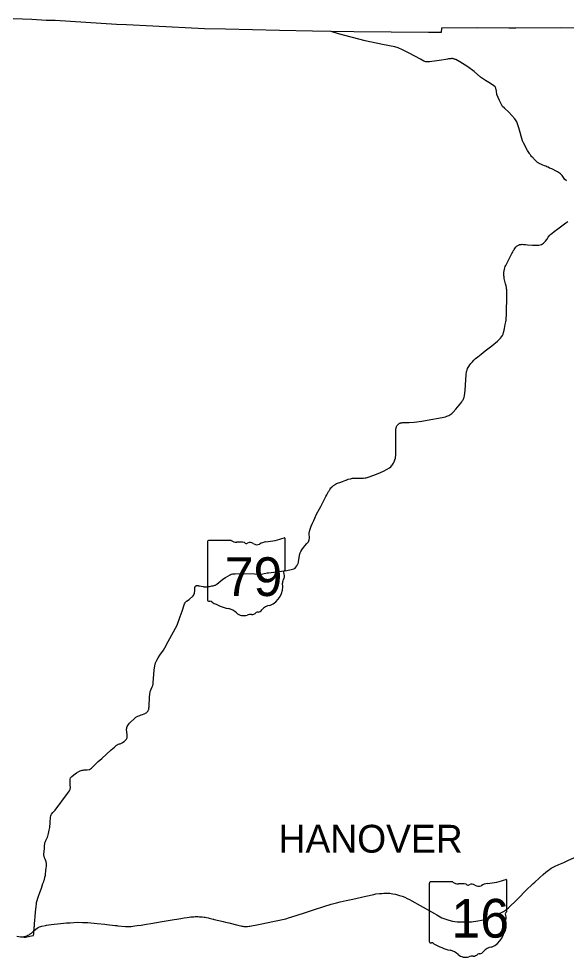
# Model space of a CAD drawing. Extents: x 1761803 to 2441803, y 509895 to 949895.
# Drawn here: x 1999264 to 2038611, y 844157 to 911653 of the extents above; entities that cross this region are included whole.
import ezdxf

# ---------------------------------------------------------------- set-up
doc = ezdxf.new("R2010")
doc.units = 0
for name, color, linetype in [('GM_X_County', 7, 'Continuous'), ('GM_X_County_Road', 7, 'Continuous'), ('GM_X_Minor_Lake', 7, 'Continuous'), ('GM_X_Township_Road', 7, 'Continuous')]:
    doc.layers.add(name, color=color, linetype=linetype)

msp = doc.modelspace()

# ---------------------------------------------------------------- linework, layer by layer
at = {"layer": 'GM_X_County'}
msp.add_lwpolyline([(2053400, 910687), (2048066, 910835), (2042725, 910935), (2038298, 911006), (2034985, 910966), (2034493, 910970), (2032253, 910990), (2029643, 910984), (2029631, 910665), (2029362, 910671), (2028709, 910661), (2023356, 910714), (2021728, 910742), (2020383, 910765), (2017999, 910806), (2014117, 910901), (2012614, 910938), (2008904, 911114), (2007002, 911215), (2006296, 911251), (2001880, 911522), (2001221, 911534), (2000194, 911593), (1998869, 911653)], dxfattribs=at)
at = {"layer": 'GM_X_County_Road'}
msp.add_line((2022502, 852839), (2022502, 852839), dxfattribs=at)
msp.add_line((2022502, 852839), (2022502, 852839), dxfattribs=at)
msp.add_line((2022502, 852839), (2022502, 852839), dxfattribs=at)
at = {"layer": 'GM_X_Minor_Lake'}
for points in [[(2038621, 899990), (2038489, 900117), (2038405, 900228), (2038314, 900373), (2038192, 900506), (2037995, 900646), (2037588, 900856), (2037420, 900914), (2037310, 900968), (2037219, 901010), (2037143, 901046), (2037055, 901079), (2036941, 901125), (2036843, 901162), (2036776, 901191), (2036722, 901216), (2036672, 901241), (2036631, 901265), (2036588, 901290), (2036550, 901322), (2036488, 901375), (2036459, 901404), (2036416, 901447), (2036374, 901490), (2036340, 901532), (2036268, 901599), (2036225, 901642), (2036166, 901707), (2036119, 901758), (2036077, 901810), (2036033, 901866), (2035996, 901920), (2035967, 901971), (2035831, 902189), (2035546, 902727), (2035474, 902862), (2035199, 903805), (2035071, 904238), (2034908, 904460), (2034490, 904935), (2034177, 905221), (2034031, 905349), (2033809, 905765), (2033616, 906198), (2033604, 906450), (2033562, 906659), (2033506, 906747), (2033414, 906831), (2033171, 906987), (2032809, 907211), (2032455, 907459), (2031990, 907857), (2031540, 908195), (2030955, 908563), (2030673, 908714), (2030634, 908735), (2030581, 908755), (2030522, 908772), (2030481, 908781), (2030432, 908784), (2030366, 908787), (2030311, 908783), (2030246, 908777), (2030160, 908764), (2030070, 908750), (2029959, 908734), (2029654, 908686), (2029302, 908633), (2028789, 908552), (2028645, 908551), (2028515, 908560), (2028381, 908609), (2028126, 908739), (2027312, 909168), (2026847, 909423), (2026534, 909571), (2026283, 909638), (2025407, 909794), (2024156, 910073), (2022247, 910574), (2021728, 910742)], [(2022788, 878480), (2022937, 878529), (2023097, 878573), (2023188, 878591), (2023239, 878601), (2023366, 878610), (2023560, 878614), (2023847, 878617), (2024051, 878620), (2024168, 878630), (2024240, 878642), (2024439, 878701), (2024772, 878836), (2025099, 878956), (2025469, 879109), (2025731, 879251), (2025919, 879366), (2026006, 879438), (2026061, 879496), (2026100, 879540), (2026193, 879694), (2026247, 879789), (2026304, 879928), (2026332, 880055), (2026347, 880134), (2026360, 880239), (2026364, 880430), (2026364, 881533), (2026367, 882066), (2026370, 882127), (2026375, 882165), (2026382, 882207), (2026392, 882248), (2026402, 882291), (2026420, 882326), (2026441, 882367), (2026463, 882399), (2026481, 882431), (2026501, 882456), (2026523, 882477), (2026546, 882501), (2026576, 882524), (2026609, 882546), (2026637, 882560), (2026672, 882575), (2026707, 882586), (2026740, 882593), (2026784, 882602), (2026836, 882608), (2026946, 882611), (2027326, 882608), (2027672, 882630), (2028226, 882720), (2028885, 882829), (2029423, 882926), (2029806, 882996), (2029939, 883030), (2030036, 883064), (2030168, 883127), (2030249, 883176), (2030391, 883273), (2030494, 883369), (2030677, 883566), (2031043, 884006), (2031111, 884095), (2031166, 884188), (2031202, 884252), (2031274, 884427), (2031303, 884527), (2031332, 884740), (2031350, 884909), (2031373, 885324), (2031412, 886042), (2031434, 886274), (2031481, 886391), (2031524, 886491), (2031618, 886652), (2031692, 886758), (2031764, 886852), (2031877, 886974), (2031981, 887090), (2032095, 887209), (2032248, 887341), (2032499, 887540), (2032787, 887772), (2033267, 888121), (2033669, 888462), (2033799, 888575), (2033893, 888674), (2033962, 888782), (2034021, 888881), (2034067, 888977), (2034104, 889100), (2034149, 889252), (2034179, 889378), (2034234, 889676), (2034266, 889847), (2034288, 889978), (2034304, 890109), (2034315, 890326), (2034321, 890678), (2034336, 891512), (2034339, 891965), (2034333, 892152), (2034328, 892223), (2034316, 892314), (2034288, 892441), (2034242, 892599), (2034202, 892776), (2034159, 892972), (2034140, 893085), (2034131, 893161), (2034126, 893263), (2034119, 893404), (2034140, 893523), (2034164, 893637), (2034193, 893738), (2034233, 893847), (2034259, 893899), (2034705, 894762), (2034764, 894873), (2034807, 894956), (2034834, 895008), (2034866, 895065), (2034913, 895142), (2034958, 895203), (2034995, 895244), (2035029, 895276), (2035060, 895303), (2035089, 895324), (2035129, 895351), (2035180, 895377), (2035218, 895393), (2035258, 895407), (2035304, 895418), (2035343, 895424), (2035387, 895428), (2035437, 895430), (2035529, 895423), (2035600, 895419), (2035691, 895412), (2035833, 895397), (2036192, 895380), (2036404, 895370), (2036648, 895370), (2036732, 895383), (2036823, 895420), (2036911, 895465), (2036973, 895508), (2037060, 895583), (2037111, 895646), (2037220, 895786), (2037322, 895938), (2037435, 896079), (2037514, 896154), (2037572, 896204), (2037742, 896346), (2038002, 896545), (2038385, 896832), (2038580, 896972), (2038719, 897066)], [(2021768, 877981), (2021814, 878023), (2021873, 878073), (2021921, 878110), (2021968, 878142), (2022035, 878182), (2022105, 878219), (2022242, 878275), (2022347, 878312), (2022521, 878372), (2022763, 878472), (2022788, 878480)], [(2019302, 872412), (2019318, 872441), (2019335, 872484), (2019366, 872562), (2019375, 872628), (2019394, 872735), (2019441, 873048), (2019468, 873160), (2019491, 873233), (2019546, 873334), (2019605, 873448), (2019665, 873541), (2019744, 873640), (2019832, 873752), (2019979, 873919), (2020078, 874038), (2020134, 874176), (2020154, 874316), (2020149, 874407), (2020144, 874511), (2020140, 874597), (2020144, 874693), (2020154, 874762), (2020186, 874873), (2020234, 875015), (2020290, 875165), (2020376, 875368), (2020462, 875573), (2020532, 875737), (2020672, 876025), (2020879, 876403), (2020971, 876578), (2021072, 876778), (2021116, 876862), (2021208, 877044), (2021335, 877283), (2021397, 877403), (2021457, 877511), (2021528, 877645), (2021564, 877708), (2021592, 877754), (2021609, 877782), (2021653, 877846), (2021702, 877911), (2021757, 877971), (2021768, 877981)], [(2001335, 852807), (2001354, 852859), (2001385, 852955), (2001408, 853047), (2001457, 853297), (2001495, 853490), (2001523, 853839), (2001543, 854233), (2001559, 854323), (2001587, 854391), (2001625, 854443), (2001722, 854560), (2001877, 854725), (2002763, 855932), (2002918, 856132), (2002941, 856176), (2002957, 856217), (2002963, 856253), (2002970, 856353), (2002968, 856531), (2002958, 856763), (2002955, 856808), (2002953, 856859), (2002961, 856971), (2002991, 857069), (2003081, 857163), (2003227, 857287), (2003419, 857426), (2003580, 857522), (2003664, 857561), (2003739, 857589), (2003816, 857601), (2003887, 857611), (2003973, 857628), (2004060, 857638), (2004174, 857643), (2004339, 857670), (2004411, 857703), (2004481, 857746), (2004595, 857854), (2004772, 858042), (2004969, 858225), (2005222, 858452), (2005912, 859075), (2006139, 859277), (2006258, 859374), (2006305, 859413), (2006341, 859436), (2006425, 859473), (2006482, 859494), (2006551, 859515), (2006648, 859555), (2006683, 859567), (2006730, 859595), (2006829, 859673), (2006956, 859790), (2007006, 859849), (2007033, 859891), (2007047, 859931), (2007052, 859984), (2007047, 860188), (2007035, 860337), (2007014, 860569), (2007025, 860623), (2007035, 860686), (2007061, 860753), (2007102, 860825), (2007156, 860907), (2007231, 860983), (2007631, 861373), (2007682, 861412), (2007718, 861436), (2007764, 861469), (2007816, 861495), (2007882, 861523), (2007965, 861550), (2008063, 861588), (2008165, 861624), (2008280, 861666), (2008348, 861697), (2008383, 861716), (2008419, 861741), (2008461, 861769), (2008494, 861796), (2008523, 861827), (2008555, 861868), (2008572, 861902), (2008591, 861939), (2008605, 861984), (2008613, 862030), (2008620, 862101), (2008626, 862177), (2008629, 862210), (2008671, 862852), (2008695, 863076), (2008701, 863219), (2008712, 863263), (2008736, 863325), (2008776, 863436), (2008849, 863595), (2008895, 863699), (2008907, 863751), (2008915, 863795), (2008915, 863899), (2008939, 864205), (2008999, 864807), (2009038, 865116), (2009091, 865329), (2009186, 865527), (2009279, 865695), (2009391, 865872), (2009656, 866240), (2009773, 866413), (2010012, 866865), (2010655, 868051), (2010854, 868658), (2010996, 869056), (2011140, 869496), (2011176, 869579), (2011217, 869644), (2011252, 869691), (2011324, 869759), (2011500, 869896), (2011804, 870157), (2011849, 870218), (2011878, 870281), (2011889, 870338), (2011911, 870550), (2011922, 870745), (2011929, 870777), (2011939, 870801), (2011953, 870826), (2011967, 870845), (2011993, 870866), (2012017, 870879), (2012048, 870886), (2012085, 870890), (2012114, 870888), (2012151, 870883), (2012192, 870878), (2012244, 870866), (2012378, 870841), (2012507, 870815), (2012573, 870803), (2012632, 870795), (2012685, 870790), (2012719, 870790), (2012738, 870791), (2012829, 870804), (2012883, 870814), (2012980, 870831), (2013139, 870861), (2013242, 870880), (2013309, 870893), (2013357, 870905), (2013398, 870920), (2013437, 870938), (2013465, 870957), (2013506, 870989), (2013924, 871347), (2014120, 871466), (2014457, 871659), (2014537, 871697), (2014630, 871726), (2014807, 871742), (2015208, 871755), (2016207, 871726), (2016462, 871716), (2016573, 871715), (2016688, 871707), (2016811, 871723), (2017111, 871799), (2017209, 871814), (2018334, 871942), (2018537, 871974), (2018852, 872039), (2019036, 872083), (2019088, 872104), (2019127, 872133), (2019188, 872208), (2019246, 872311), (2019302, 872412)], [(2001120, 852189), (2001130, 852306), (2001141, 852391), (2001152, 852428), (2001173, 852477), (2001212, 852559), (2001331, 852797), (2001335, 852807)], [(2001219, 850469), (2001223, 850511), (2001249, 850765), (2001251, 850845), (2001248, 850910), (2001233, 851009), (2001206, 851101), (2001158, 851212), (2001123, 851296), (2001079, 851419), (2001070, 851476), (2001064, 851523), (2001063, 851562), (2001102, 851973), (2001120, 852189)], [(2037403, 850466), (2037527, 850555), (2037760, 850689), (2038073, 850829), (2038433, 850980), (2038782, 851135), (2039157, 851294), (2039706, 851526), (2040851, 852049), (2041140, 852168), (2041400, 852254), (2041527, 852289), (2041662, 852320), (2041799, 852350), (2041881, 852360), (2042072, 852392), (2042412, 852415), (2043160, 852462), (2043202, 852465)], [(2001054, 849604), (2001072, 849647), (2001101, 849740), (2001146, 849916), (2001163, 849984), (2001174, 850064), (2001183, 850138), (2001210, 850381), (2001219, 850469)], [(2036673, 849853), (2036685, 849865), (2036944, 850108), (2037153, 850275), (2037326, 850411), (2037403, 850466)], [(2036246, 849457), (2036361, 849564), (2036673, 849853)], [(2000391, 846435), (2000393, 846460), (2000402, 846561), (2000427, 846824), (2000446, 847057), (2000476, 847416), (2000507, 847774), (2000529, 848028), (2000541, 848098), (2000558, 848172), (2000651, 848465), (2000776, 848805), (2000885, 849117), (2000997, 849457), (2001034, 849558), (2001054, 849604)], [(2030872, 846699), (2031039, 846699), (2031442, 846699), (2031807, 846712), (2032262, 846771), (2032512, 846811), (2032745, 846866), (2032956, 846945), (2033182, 847047), (2033480, 847184), (2033922, 847357), (2034093, 847450), (2034238, 847536), (2034454, 847713), (2035077, 848318), (2035815, 849044), (2036122, 849341), (2036246, 849457)], [(2018732, 847005), (2018817, 847030), (2019802, 847351), (2020435, 847567), (2021180, 847806), (2021712, 847969), (2022090, 848068), (2022368, 848139), (2022797, 848239), (2023271, 848335), (2024208, 848554), (2024772, 848676), (2024927, 848706), (2025195, 848739), (2025369, 848748), (2025508, 848759), (2025709, 848764), (2025881, 848756)], [(2025881, 848756), (2025933, 848753), (2026039, 848740)], [(2026039, 848740), (2026145, 848727), (2026333, 848687), (2026637, 848605), (2026816, 848546), (2027007, 848466), (2027187, 848391), (2027340, 848314), (2027513, 848224), (2028108, 847882), (2029144, 847302), (2029323, 847195), (2029677, 847000), (2029954, 846884), (2030176, 846811), (2030435, 846743), (2030768, 846699), (2030872, 846699)], [(2011660, 847061), (2011699, 847065), (2011835, 847073), (2011939, 847078), (2012049, 847079), (2012153, 847077), (2012246, 847072), (2012328, 847065), (2012453, 847055), (2012583, 847040), (2012654, 847029), (2012761, 847011), (2012874, 846985), (2012958, 846966), (2013247, 846893), (2013271, 846887)], [(2000356, 846053), (2000501, 846180), (2000580, 846241), (2000659, 846295), (2000761, 846343), (2000844, 846370), (2000929, 846393), (2001195, 846447)], [(2000356, 846053), (2000366, 846170), (2000378, 846292), (2000380, 846320), (2000388, 846400), (2000391, 846435)], [(2001195, 846447), (2001267, 846462), (2001595, 846506), (2002261, 846586), (2002701, 846626), (2002950, 846638), (2003483, 846667), (2003852, 846662), (2004162, 846651), (2004238, 846648), (2004886, 846591)], [(2004886, 846591), (2005460, 846529), (2005589, 846513)], [(2005589, 846513), (2006190, 846442), (2006310, 846431)], [(2006310, 846431), (2006394, 846423), (2006924, 846359), (2007092, 846361), (2007239, 846363), (2007309, 846369)], [(2007309, 846369), (2007347, 846372), (2007461, 846385), (2007606, 846403), (2007772, 846428), (2008058, 846474), (2008302, 846515)], [(2008302, 846515), (2008907, 846618), (2009011, 846635)], [(2009011, 846635), (2009720, 846750), (2010433, 846866), (2010614, 846897), (2010914, 846946), (2011161, 846986), (2011372, 847022), (2011510, 847043), (2011625, 847057), (2011648, 847059), (2011660, 847061)], [(2013271, 846887), (2013301, 846879), (2013421, 846849), (2013956, 846719), (2014129, 846678), (2014371, 846619), (2015009, 846462), (2015105, 846438), (2015221, 846411), (2015300, 846397), (2015370, 846385), (2015448, 846377), (2015528, 846371), (2015571, 846368), (2015633, 846371)], [(2015633, 846371), (2015642, 846371), (2015707, 846374), (2015822, 846384), (2015881, 846392), (2015999, 846414), (2016379, 846485), (2016841, 846575), (2016959, 846602), (2018458, 846927), (2018732, 847005)], [(1999577, 845622), (1999653, 845648), (1999745, 845674), (1999833, 845705), (1999907, 845735), (2000017, 845779), (2000094, 845828), (2000183, 845892), (2000356, 846053)], [(2000330, 845714), (2000341, 845849), (2000356, 846053)], [(1999134, 845664), (1999268, 845647), (1999386, 845629), (1999484, 845621), (1999577, 845622)], [(1999577, 845622), (1999643, 845610), (1999681, 845603), (1999741, 845599), (1999853, 845612), (1999973, 845637), (2000186, 845692), (2000267, 845711), (2000330, 845714)]]:
    msp.add_lwpolyline(points, dxfattribs=at)
at = {"layer": 'GM_X_Township_Road'}
for p, q in [((2014525, 874138), (2012894, 874138)), ((2018408, 872032), (2018408, 874243)), ((2012839, 874066), (2012839, 869839)), ((2018408, 872033), (2018408, 872032)), ((2028772, 849495), (2028772, 845268)), ((2030458, 849568), (2028827, 849568)), ((2034341, 847461), (2034341, 849672)), ((2034341, 847462), (2034341, 847461))]:
    msp.add_line(p, q, dxfattribs=at)
for centre, radius, start, end in [((2012903, 874075), 64.5, 98.1301, 188.1301), ((2014913, 874629), 626, 231.61951, 271.11188), ((2016424, 879901), 5905, 275.84447, 288.90645), ((2018346, 874252), 62, 351.86209, 97.738), ((2015121, 871766), 2246, 80.48669, 94.98827), ((2015631, 874097), 181, 219.79206, 297.10237), ((2015896, 873608), 375, 54.46668, 119.14113), ((2016380, 874278), 452, 233.85621, 294.82819), ((2017178, 872848), 1188, 97.34618, 120.76885), ((2018630, 871107), 419, 136.8065, 186.92959), ((2018394, 871870), 95.9, 107.94398, 210.33697), ((2017783, 871590), 576, 340.03296, 23.64957), ((2018342, 872024), 66.3, 289.60381, 7.73413), ((2016755, 870826), 1477, 292.30889, 8.98584), ((2012904, 869830), 65.1, 171.95839, 258.30661), ((2012914, 870262), 497, 267.33899, 280.60386), ((2013015, 869595), 179, 29.74838, 93.27175), ((2015276, 873393), 4265, 240.41292, 257.1985), ((2017378, 868653), 809, 94.40312, 142.57675), ((2014005, 867940), 1334, 47.18416, 75.83597), ((2015448, 869574), 847, 230.70037, 286.29184), ((2015937, 868113), 696, 85.69512, 111.20995), ((2015999, 869258), 451, 268.77702, 315.54927), ((2016407, 868849), 127, 65.75173, 132.64842), ((2016353, 869430), 477, 282.87319, 323.27711), ((2028836, 849504), 64.5, 98.1301, 188.1301), ((2030846, 850058), 626, 231.61951, 271.11188), ((2031054, 847195), 2246, 80.48669, 94.98827), ((2031564, 849526), 181, 219.79206, 297.10237), ((2031829, 849037), 375, 54.46668, 119.14113), ((2032313, 849707), 452, 233.85621, 294.82819), ((2033111, 848277), 1188, 97.34618, 120.76885), ((2032358, 855330), 5905, 275.84447, 288.90645), ((2034279, 849681), 62, 351.86209, 97.738), ((2034327, 847299), 95.9, 107.94398, 210.33697), ((2033716, 847020), 576, 340.03296, 23.64957), ((2034275, 847453), 66.3, 289.60381, 7.73413), ((2032688, 846255), 1477, 292.30889, 8.98584), ((2034563, 846536), 419, 136.8065, 186.92959), ((2028837, 845259), 65.1, 171.95839, 258.30661), ((2028847, 845691), 497, 267.33899, 280.60386), ((2028948, 845024), 179, 29.74838, 93.27175), ((2031209, 848822), 4265, 240.41292, 257.1985), ((2029938, 843369), 1334, 47.18416, 75.83597), ((2032340, 844278), 127, 65.75173, 132.64842), ((2032286, 844859), 477, 282.87319, 323.27711), ((2033311, 844082), 809, 94.40312, 142.57675), ((2031381, 845003), 847, 230.70037, 286.29184), ((2031870, 843542), 696, 85.69512, 111.20995), ((2031932, 844687), 451, 268.77702, 315.54927)]:
    msp.add_arc(centre, radius, start, end, dxfattribs=at)

# ---------------------------------------------------------------- texts
at = {"layer": 'GM_X_County_Road'}
msp.add_text('HANOVER', height=2000, rotation=0.00001, dxfattribs=at).set_placement((2017941, 851680))
at = {"layer": 'GM_X_Township_Road'}
for s, p in [('79', (2014067, 870137)), ('16', (2030360, 845566))]:
    msp.add_text(s, height=2784.4, dxfattribs=at).set_placement(p)

doc.saveas('drawing.dxf')
